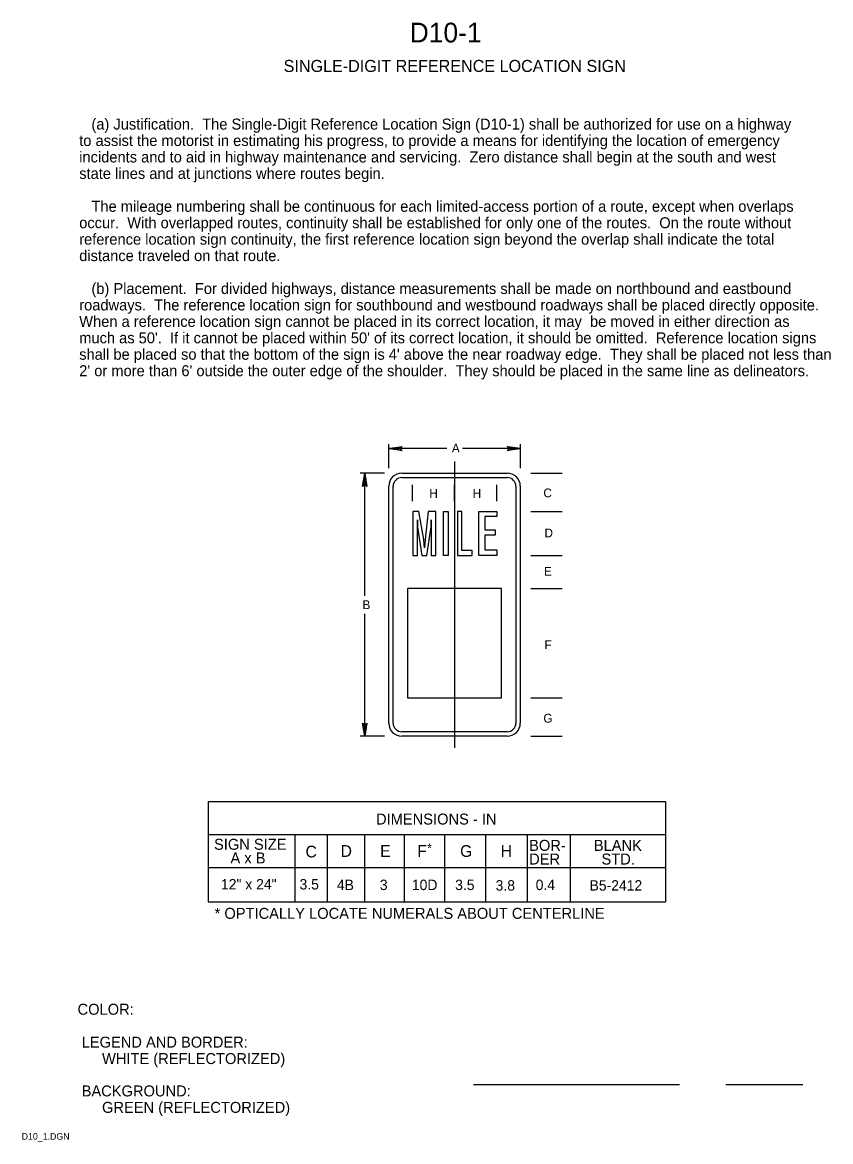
# Model space of a CAD drawing. Extents: x 0.013 to 0.197, y 0.004 to 0.259.
import ezdxf

# ---------------------------------------------------------------- set-up
doc = ezdxf.new("R2010")
doc.units = 0
for name, color, linetype in [('1', 7, 'Continuous'), ('2', 7, 'Continuous'), ('3', 7, 'Continuous')]:
    doc.layers.add(name, color=color, linetype=linetype)

# ---------------------------------------------------------------- blocks, each defined once
blk = doc.blocks.new('RARROW')
at = {"layer": '3'}
for p, q in [((-2.156, 0.285), (-2.2665, 0.384625)), ((-2.2665, 0.384625), (0, 0)), ((0, 0), (-2.2665, -0.379125)), ((-2.156, 0.285), (-2.075625, 0.12075)), ((0, 0), (-2.156, 0.285)), ((-2.14975, -0.2705), (0, 0)), ((-2.075625, 0.12075), (0, 0)), ((0, 0), (-2.074, -0.108)), ((-2.2665, -0.379125), (-2.14975, -0.2705)), ((-2.074, -0.108), (-2.14975, -0.2705))]:
    blk.add_line(p, q, dxfattribs=at)

msp = doc.modelspace()

# ---------------------------------------------------------------- linework, layer by layer
at = {"layer": '1'}
for p, q in [((0.11544, 0.01695), (0.16242, 0.01695)), ((0.17295, 0.01695), (0.19056, 0.01695))]:
    msp.add_line(p, q, dxfattribs=at)
at = {"layer": '2'}
for p, q in [((0.09613, 0.1575), (0.09613, 0.163)), ((0.10938, 0.162), (0.09613, 0.162)), ((0.12613, 0.162), (0.11294, 0.162)), ((0.12613, 0.1575), (0.12613, 0.163)), ((0.0951, 0.1564), (0.0896, 0.1564)), ((0.09062, 0.12841), (0.09062, 0.1564)), ((0.1285, 0.15638), (0.13562, 0.15638)), ((0.1015, 0.15), (0.1015, 0.15375)), ((0.11113, 0.15), (0.11113, 0.15375)), ((0.12075, 0.15), (0.12075, 0.15375)), ((0.1285, 0.14763), (0.13562, 0.14763)), ((0.1285, 0.13762), (0.13562, 0.13762)), ((0.1004, 0.13012), (0.1004, 0.10512)), ((0.1218, 0.13012), (0.1004, 0.13012)), ((0.1218, 0.10512), (0.1218, 0.13012)), ((0.1285, 0.13012), (0.13562, 0.13012)), ((0.09062, 0.0964), (0.09062, 0.12428)), ((0.1004, 0.10512), (0.1218, 0.10512)), ((0.1285, 0.10512), (0.13562, 0.10512)), ((0.0951, 0.0964), (0.0896, 0.0964)), ((0.1285, 0.09638), (0.13562, 0.09638))]:
    msp.add_line(p, q, dxfattribs=at)
for points in [[(0.10163, 0.14763), (0.10163, 0.13762), (0.10263, 0.13762), (0.10263, 0.144), (0.10263, 0.14575), (0.10263, 0.14413), (0.10363, 0.13762), (0.10475, 0.13762), (0.10575, 0.14413), (0.10575, 0.14575), (0.10575, 0.144), (0.10575, 0.13762), (0.10687, 0.13762), (0.10687, 0.14763), (0.10512, 0.14763), (0.10437, 0.14125), (0.10425, 0.13937), (0.10412, 0.14125), (0.103, 0.14763), (0.10163, 0.14763)], [(0.10862, 0.13762), (0.10862, 0.14763), (0.10963, 0.14763), (0.10963, 0.13762), (0.10862, 0.13762)], [(0.11175, 0.14763), (0.11175, 0.13762), (0.11513, 0.13762), (0.11513, 0.13875), (0.11275, 0.13875), (0.11275, 0.14763), (0.11175, 0.14763)], [(0.11663, 0.13762), (0.11663, 0.14763), (0.12075, 0.14763), (0.12075, 0.1465), (0.118, 0.1465), (0.118, 0.1435), (0.12037, 0.1435), (0.12037, 0.14225), (0.118, 0.14225), (0.118, 0.13887), (0.12075, 0.13887), (0.12075, 0.13762), (0.11663, 0.13762)]]:
    msp.add_lwpolyline(points, dxfattribs=at)
at = {"layer": '3'}
for p, q in [((0.1111, 0.15905), (0.1111, 0.09373)), ((0.0991, 0.1564), (0.1231, 0.1564)), ((0.0961, 0.0994), (0.0961, 0.1534)), ((0.0971, 0.0994), (0.0971, 0.1534)), ((0.0991, 0.1554), (0.1231, 0.1554)), ((0.1251, 0.1534), (0.1251, 0.0994)), ((0.1261, 0.1534), (0.1261, 0.0994)), ((0.1231, 0.0974), (0.0991, 0.0974)), ((0.1231, 0.0964), (0.0991, 0.0964)), ((0.05494, 0.08149), (0.1592, 0.08149)), ((0.05495, 0.08151), (0.05495, 0.05862)), ((0.1592, 0.08149), (0.1592, 0.05862)), ((0.1592, 0.07387), (0.05494, 0.07387)), ((0.0747, 0.07376), (0.0747, 0.05862)), ((0.08208, 0.07389), (0.08208, 0.05862)), ((0.09058, 0.07389), (0.09058, 0.05862)), ((0.09958, 0.07389), (0.09958, 0.05862)), ((0.10883, 0.07389), (0.10883, 0.05862)), ((0.1182, 0.07389), (0.1182, 0.05862)), ((0.1277, 0.07389), (0.1277, 0.05862)), ((0.13745, 0.07389), (0.13745, 0.05862)), ((0.05494, 0.06649), (0.1592, 0.06649)), ((0.05494, 0.05862), (0.1592, 0.05862))]:
    msp.add_line(p, q, dxfattribs=at)
for centre, radius, start, end in [((0.0991, 0.1534), 0.003, 90, 180), ((0.1231, 0.1534), 0.003, 0, 90), ((0.0991, 0.1534), 0.002, 90, 180), ((0.1231, 0.1534), 0.002, 0, 90), ((0.0991, 0.0994), 0.003, 180, 270), ((0.0991, 0.0994), 0.002, 180, 270), ((0.1231, 0.0994), 0.003, 270, 0), ((0.1231, 0.0994), 0.002, 270, 0)]:
    msp.add_arc(centre, radius, start, end, dxfattribs=at)

# ---------------------------------------------------------------- block references
at = {"layer": '2', "xscale": 0.0013236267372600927, "yscale": 0.001309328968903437}
for p, rotation in [((0.09613, 0.162), 180), ((0.09062, 0.15638), 90), ((0.09062, 0.09638), -90)]:
    msp.add_blockref('RARROW', p, dxfattribs=dict(at, rotation=rotation))
msp.add_blockref('RARROW', (0.12613, 0.162), dxfattribs=at)

# ---------------------------------------------------------------- texts
at = {"layer": '1'}
for s, height, p in [('D10-1', 0.0045, (0.10088, 0.25462)), ('SINGLE-DIGIT REFERENCE LOCATION SIGN', 0.0027503, (0.07213, 0.24788)), ('COLOR:', 0.0025, (0.02513, 0.03288)), (' LEGEND AND BORDER:', 0.0024998, (0.02513, 0.02538)), ('      WHITE (REFLECTORIZED)', 0.0024998, (0.02513, 0.02163)), (' BACKGROUND:', 0.0024998, (0.02513, 0.01425)), ('      GREEN (REFLECTORIZED)', 0.0024998, (0.02513, 0.0105)), ('D10_1.DGN', 0.0015, (0.01238, 0.00438))]:
    msp.add_text(s, height=height, dxfattribs=at).set_placement(p)
at = {"layer": '2'}
for s, height, p in [('   (a) Justification.  The Single-Digit Reference Location Sign (D10-1) shall be authorized for use on a highway', 0.00249975, (0.0255, 0.23475)), ('to assist the motorist in estimating his progress, to provide a means for identifying the location of emergency', 0.00249975, (0.0255, 0.231)), ('incidents and to aid in highway maintenance and servicing.  Zero distance shall begin at the south and west', 0.00249975, (0.0255, 0.22725)), ('state lines and at junctions where routes begin.', 0.0024998, (0.0255, 0.2235)), ('   The mileage numbering shall be continuous for each limited-access portion of a route, except when overlaps', 0.00249975, (0.0255, 0.216)), ('occur.  With overlapped routes, continuity shall be established for only one of the routes.  On the route without', 0.00249975, (0.0255, 0.21225)), ('reference location sign continuity, the first reference location sign beyond the overlap shall indicate the total ', 0.00249975, (0.0255, 0.2085)), ('distance traveled on that route.', 0.0024998, (0.0255, 0.20475)), ('   (b) Placement.  For divided highways, distance measurements shall be made on northbound and eastbound', 0.00249975, (0.0255, 0.19725)), ('roadways.  The reference location sign for southbound and westbound roadways shall be placed directly opposite. ', 0.00249975, (0.0255, 0.1935)), ('When a reference location sign cannot be placed in its correct location, it may  be moved in either direction as ', 0.00249975, (0.0255, 0.18975)), ("much as 50'.  If it cannot be placed within 50' of its correct location, it should be omitted.  Reference location signs ", 0.00249975, (0.0255, 0.186)), ("shall be placed so that the bottom of the sign is 4' above the near roadway edge.  They shall be placed not less than ", 0.00249975, (0.0255, 0.18225)), ("2' or more than 6' outside the outer edge of the shoulder.  They should be placed in the same line as delineators. ", 0.00249975, (0.0255, 0.1785)), ('A', 0.002, (0.1105, 0.16112)), ('H', 0.002, (0.10537, 0.15075)), ('H', 0.002, (0.11525, 0.15075)), ('C', 0.002, (0.13137, 0.15088)), ('D', 0.002, (0.13162, 0.14175)), ('E', 0.002, (0.1315, 0.133)), ('B', 0.002, (0.09012, 0.12538)), ('F', 0.002, (0.13162, 0.11625)), ('G', 0.002, (0.13137, 0.0995))]:
    msp.add_text(s, height=height, dxfattribs=at).set_placement(p)
at = {"layer": '3'}
for s, height, p in [('DIMENSIONS - IN', 0.0024998, (0.0932, 0.07625)), ('SIGN SIZE', 0.0025, (0.05625, 0.0705)), ('D', 0.00267, (0.08513, 0.06888)), ('E', 0.00267, (0.09413, 0.06888)), ('F', 0.00267, (0.10263, 0.06888)), ('*', 0.002, (0.10487, 0.06988)), ('G', 0.00267, (0.11238, 0.06888)), ('H', 0.00267, (0.12162, 0.06888)), ('BOR-', 0.0025, (0.12812, 0.07025)), ('BLANK', 0.0025, (0.14288, 0.07025)), ('A x B', 0.0025, (0.06, 0.06738)), ('C', 0.00267, (0.07712, 0.06875)), ('DER', 0.0025, (0.12812, 0.06713)), ('STD.', 0.0025, (0.14463, 0.06713)), ('12" x 24"', 0.002375, (0.05784, 0.06144)), ('3.5', 0.002375, (0.07575, 0.06144)), ('4B', 0.002375, (0.08427, 0.06131)), ('3', 0.00238, (0.09406, 0.06131)), ('10D', 0.002375, (0.10138, 0.06131)), ('3.5', 0.002375, (0.11125, 0.06131)), ('3.8', 0.002375, (0.12048, 0.06119)), ('0.4', 0.002375, (0.12961, 0.06131)), ('B5-2412', 0.002375, (0.1419, 0.06119)), ('* OPTICALLY LOCATE NUMERALS ABOUT CENTERLINE', 0.0024998, (0.05638, 0.05475))]:
    msp.add_text(s, height=height, dxfattribs=at).set_placement(p)

doc.saveas('drawing.dxf')
